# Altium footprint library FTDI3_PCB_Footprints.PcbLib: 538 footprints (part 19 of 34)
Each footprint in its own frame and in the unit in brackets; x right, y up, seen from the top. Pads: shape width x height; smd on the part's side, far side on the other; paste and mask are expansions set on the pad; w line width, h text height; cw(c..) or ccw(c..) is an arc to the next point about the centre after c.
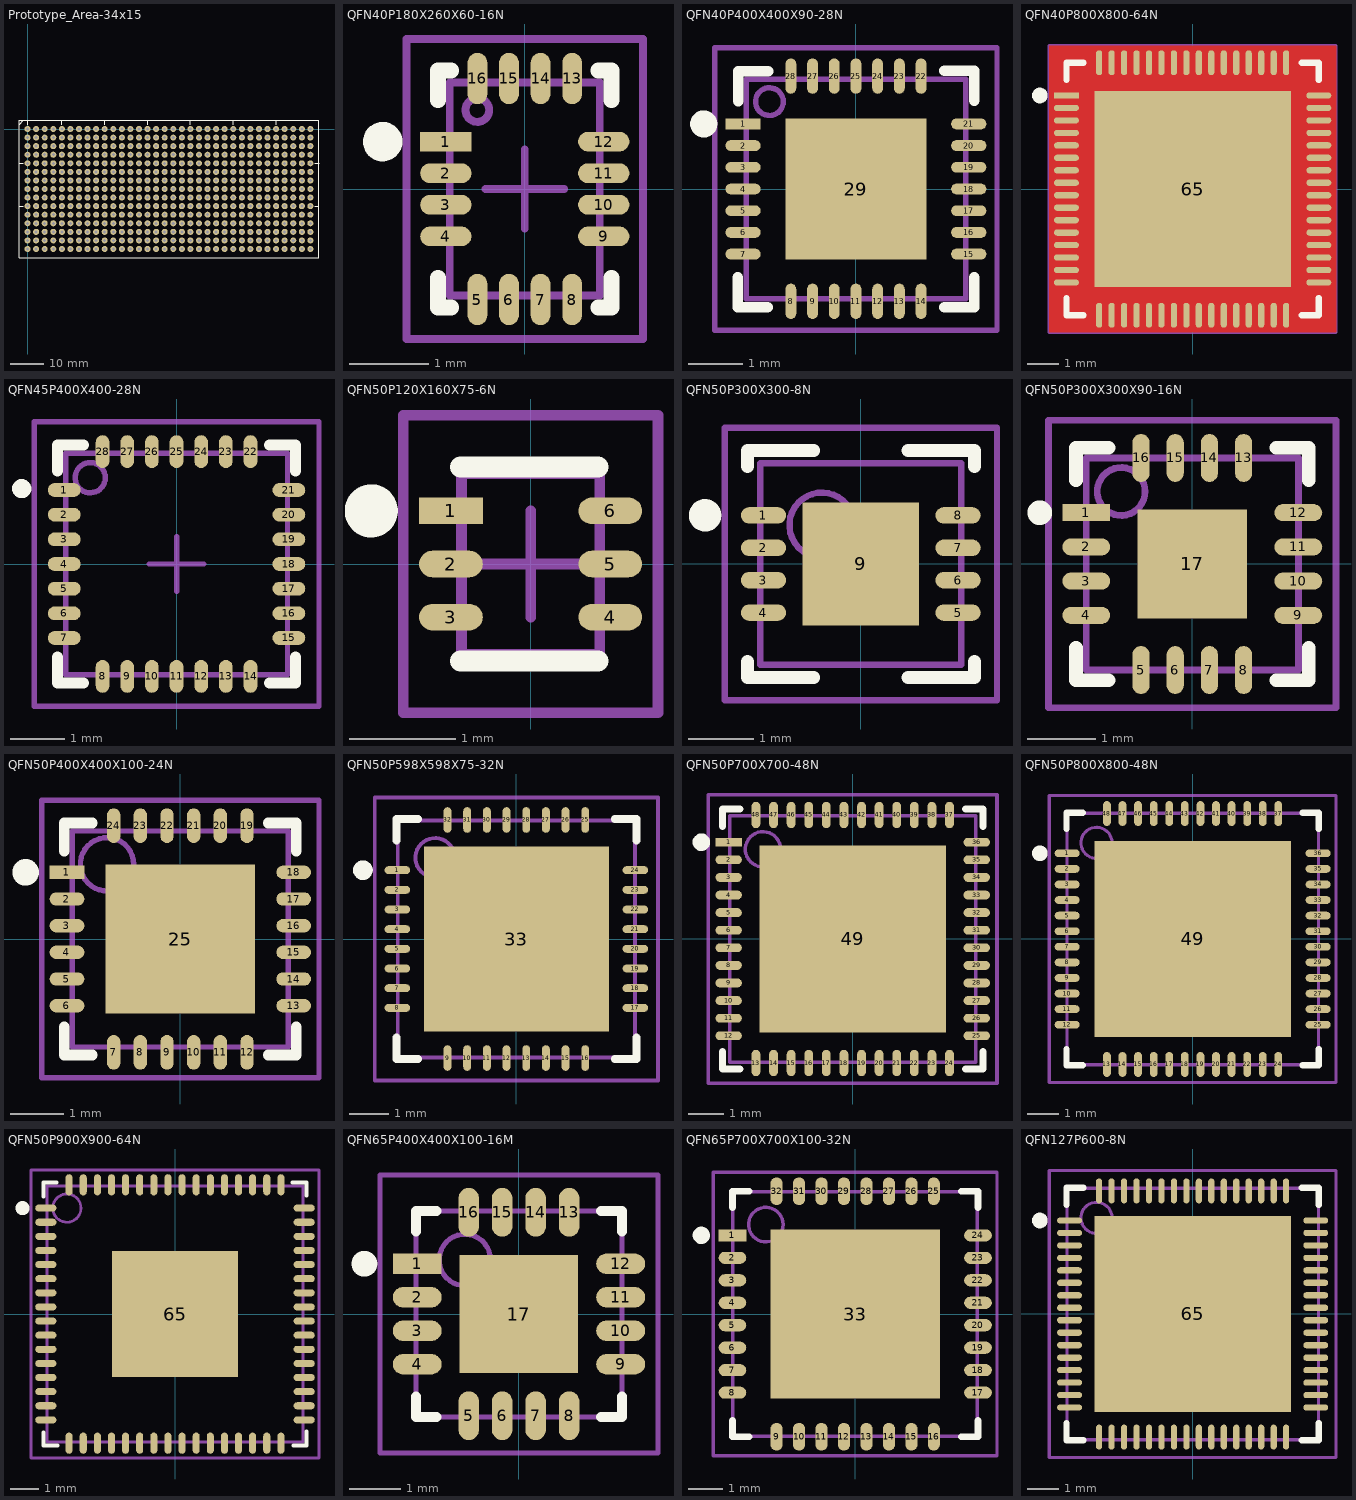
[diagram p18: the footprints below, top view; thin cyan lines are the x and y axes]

## Prototype_Area-34x15 [mm] "Prototype area; 34 cols x 15 rows"
pads (510):
  round 1.8 hole 0.9: 1(0,0) 2(2.54,0) 3(5.08,0) 4(7.62,0) 5(10.16,0) 6(12.7,0) 7(15.24,0) 8(17.78,0) 9(20.32,0) 10(22.86,0) 11(25.4,0) 12(27.94,0) 13(30.48,0) 14(33.02,0) 15(35.56,0) 16(38.1,0) 17(40.64,0) 18(43.18,0) 19(45.72,0) 20(48.26,0) 21(50.8,0) 22(53.34,0) 23(55.88,0) 24(58.42,0) 25(60.96,0) 26(63.5,0) 27(66.04,0) 28(68.58,0) 29(71.12,0) 30(73.66,0) 31(76.2,0) 32(78.74,0) 33(81.28,0) 34(83.82,0) ""(0,-35.56) ""(0,-33.02) ""(0,-30.48) ""(0,-27.94) ""(0,-25.4) ""(0,-22.86) ""(0,-20.32) ""(0,-17.78) ""(0,-15.24) ""(0,-12.7) ""(0,-10.16) ""(0,-7.62) ""(0,-5.08) ""(0,-2.54) ""(2.54,-35.56) ""(2.54,-33.02) ""(2.54,-30.48) ""(2.54,-27.94) ""(2.54,-25.4) ""(2.54,-22.86) ""(2.54,-20.32) ""(2.54,-17.78) ""(2.54,-15.24) ""(2.54,-12.7) ""(2.54,-10.16) ""(2.54,-7.62) ""(2.54,-5.08) ""(2.54,-2.54) ""(5.08,-35.56) ""(5.08,-33.02) ""(5.08,-30.48) ""(5.08,-27.94) ""(5.08,-25.4) ""(5.08,-22.86) ""(5.08,-20.32) ""(5.08,-17.78) ""(5.08,-15.24) ""(5.08,-12.7) ""(5.08,-10.16) ""(5.08,-7.62) ""(5.08,-5.08) ""(5.08,-2.54) ""(7.62,-35.56) ""(7.62,-33.02) ""(7.62,-30.48) ""(7.62,-27.94) ""(7.62,-25.4) ""(7.62,-22.86) ""(7.62,-20.32) ""(7.62,-17.78) ""(7.62,-15.24) ""(7.62,-12.7) ""(7.62,-10.16) ""(7.62,-7.62) ""(7.62,-5.08) ""(7.62,-2.54) ""(10.16,-35.56) ""(10.16,-33.02) ""(10.16,-30.48) ""(10.16,-27.94) ""(10.16,-25.4) ""(10.16,-22.86) ""(10.16,-20.32) ""(10.16,-17.78) ""(10.16,-15.24) ""(10.16,-12.7) ""(10.16,-10.16) ""(10.16,-7.62) ""(10.16,-5.08) ""(10.16,-2.54) ""(12.7,-35.56) ""(12.7,-33.02) ""(12.7,-30.48) ""(12.7,-27.94) ""(12.7,-25.4) ""(12.7,-22.86) ""(12.7,-20.32) ""(12.7,-17.78) ""(12.7,-15.24) ""(12.7,-12.7) ""(12.7,-10.16) ""(12.7,-7.62) ""(12.7,-5.08) ""(12.7,-2.54) ""(15.24,-35.56) ""(15.24,-33.02) ""(15.24,-30.48) ""(15.24,-27.94) ""(15.24,-25.4) ""(15.24,-22.86) ""(15.24,-20.32) ""(15.24,-17.78) ""(15.24,-15.24) ""(15.24,-12.7) ""(15.24,-10.16) ""(15.24,-7.62) ""(15.24,-5.08) ""(15.24,-2.54) ""(17.78,-35.56) ""(17.78,-33.02) ""(17.78,-30.48) ""(17.78,-27.94) ""(17.78,-25.4) ""(17.78,-22.86) ""(17.78,-20.32) ""(17.78,-17.78) ""(17.78,-15.24) ""(17.78,-12.7) ""(17.78,-10.16) ""(17.78,-7.62) ""(17.78,-5.08) ""(17.78,-2.54) ""(20.32,-35.56) ""(20.32,-33.02) ""(20.32,-30.48) ""(20.32,-27.94) ""(20.32,-25.4) ""(20.32,-22.86) ""(20.32,-20.32) ""(20.32,-17.78) ""(20.32,-15.24) ""(20.32,-12.7) ""(20.32,-10.16) ""(20.32,-7.62) ""(20.32,-5.08) ""(20.32,-2.54) ""(22.86,-35.56) ""(22.86,-33.02) ""(22.86,-30.48) ""(22.86,-27.94) ""(22.86,-25.4) ""(22.86,-22.86) ""(22.86,-20.32) ""(22.86,-17.78) ""(22.86,-15.24) ""(22.86,-12.7) ""(22.86,-10.16) ""(22.86,-7.62) ""(22.86,-5.08) ""(22.86,-2.54) ""(25.4,-35.56) ""(25.4,-33.02) ""(25.4,-30.48) ""(25.4,-27.94) ""(25.4,-25.4) ""(25.4,-22.86) ""(25.4,-20.32) ""(25.4,-17.78) ""(25.4,-15.24) ""(25.4,-12.7) ""(25.4,-10.16) ""(25.4,-7.62) ""(25.4,-5.08) ""(25.4,-2.54) ""(27.94,-35.56) ""(27.94,-33.02) ""(27.94,-30.48) ""(27.94,-27.94) ""(27.94,-25.4) ""(27.94,-22.86) ""(27.94,-20.32) ""(27.94,-17.78) ""(27.94,-15.24) ""(27.94,-12.7) ""(27.94,-10.16) ""(27.94,-7.62) ""(27.94,-5.08) ""(27.94,-2.54) ""(30.48,-35.56) ""(30.48,-33.02) ""(30.48,-30.48) ""(30.48,-27.94) ""(30.48,-25.4) ""(30.48,-22.86) ""(30.48,-20.32) ""(30.48,-17.78) ""(30.48,-15.24) ""(30.48,-12.7) ""(30.48,-10.16) ""(30.48,-7.62) ""(30.48,-5.08) ""(30.48,-2.54) ""(33.02,-35.56) ""(33.02,-33.02) ""(33.02,-30.48) ""(33.02,-27.94) ""(33.02,-25.4) ""(33.02,-22.86) ""(33.02,-20.32) ""(33.02,-17.78) ""(33.02,-15.24) ""(33.02,-12.7) ""(33.02,-10.16) ""(33.02,-7.62) ""(33.02,-5.08) ""(33.02,-2.54) ""(35.56,-35.56) ""(35.56,-33.02) ""(35.56,-30.48) ""(35.56,-27.94) ""(35.56,-25.4) ""(35.56,-22.86) ""(35.56,-20.32) ""(35.56,-17.78) ""(35.56,-15.24) ""(35.56,-12.7) ""(35.56,-10.16) ""(35.56,-7.62) ""(35.56,-5.08) ""(35.56,-2.54) ""(38.1,-35.56) ""(38.1,-33.02) ""(38.1,-30.48) ""(38.1,-27.94) ""(38.1,-25.4) ""(38.1,-22.86) ""(38.1,-20.32) ""(38.1,-17.78) ""(38.1,-15.24) ""(38.1,-12.7) ""(38.1,-10.16) ""(38.1,-7.62) ""(38.1,-5.08) ""(38.1,-2.54) ""(40.64,-35.56) ""(40.64,-33.02) ""(40.64,-30.48) ""(40.64,-27.94) ""(40.64,-25.4) ""(40.64,-22.86) ""(40.64,-20.32) ""(40.64,-17.78) ""(40.64,-15.24) ""(40.64,-12.7) ""(40.64,-10.16) ""(40.64,-7.62) ""(40.64,-5.08) ""(40.64,-2.54) ""(43.18,-35.56) ""(43.18,-33.02) ""(43.18,-30.48) ""(43.18,-27.94) ""(43.18,-25.4) ""(43.18,-22.86) ""(43.18,-20.32) ""(43.18,-17.78) ""(43.18,-15.24) ""(43.18,-12.7) ""(43.18,-10.16) ""(43.18,-7.62) ""(43.18,-5.08) ""(43.18,-2.54) ""(45.72,-35.56) ""(45.72,-33.02) ""(45.72,-30.48) ""(45.72,-27.94) ""(45.72,-25.4) ""(45.72,-22.86) ""(45.72,-20.32) ""(45.72,-17.78) ""(45.72,-15.24) ""(45.72,-12.7) ""(45.72,-10.16) ""(45.72,-7.62) ""(45.72,-5.08) ""(45.72,-2.54) ""(48.26,-35.56) ""(48.26,-33.02) ""(48.26,-30.48) ""(48.26,-27.94) ""(48.26,-25.4) ""(48.26,-22.86) ""(48.26,-20.32) ""(48.26,-17.78) ""(48.26,-15.24) ""(48.26,-12.7) ""(48.26,-10.16) ""(48.26,-7.62) ""(48.26,-5.08) ""(48.26,-2.54) ""(50.8,-35.56) ""(50.8,-33.02) ""(50.8,-30.48) ""(50.8,-27.94) ""(50.8,-25.4) ""(50.8,-22.86) ""(50.8,-20.32) ""(50.8,-17.78) ""(50.8,-15.24) ""(50.8,-12.7) ""(50.8,-10.16) ""(50.8,-7.62) ""(50.8,-5.08) ""(50.8,-2.54) ""(53.34,-35.56) ""(53.34,-33.02) ""(53.34,-30.48) ""(53.34,-27.94) ""(53.34,-25.4) ""(53.34,-22.86) ""(53.34,-20.32) ""(53.34,-17.78) ""(53.34,-15.24) ""(53.34,-12.7) ""(53.34,-10.16) ""(53.34,-7.62) ""(53.34,-5.08) ""(53.34,-2.54) ""(55.88,-35.56) ""(55.88,-33.02) ""(55.88,-30.48) ""(55.88,-27.94) ""(55.88,-25.4) ""(55.88,-22.86) ""(55.88,-20.32) ""(55.88,-17.78) ""(55.88,-15.24) ""(55.88,-12.7) ""(55.88,-10.16) ""(55.88,-7.62) ""(55.88,-5.08) ""(55.88,-2.54) ""(58.42,-35.56) ""(58.42,-33.02) ""(58.42,-30.48) ""(58.42,-27.94) ""(58.42,-25.4) ""(58.42,-22.86) ""(58.42,-20.32) ""(58.42,-17.78) ""(58.42,-15.24) ""(58.42,-12.7) ""(58.42,-10.16) ""(58.42,-7.62) ""(58.42,-5.08) ""(58.42,-2.54) ""(60.96,-35.56) ""(60.96,-33.02) ""(60.96,-30.48) ""(60.96,-27.94) ""(60.96,-25.4) ""(60.96,-22.86) ""(60.96,-20.32) ""(60.96,-17.78) ""(60.96,-15.24) ""(60.96,-12.7) ""(60.96,-10.16) ""(60.96,-7.62) ""(60.96,-5.08) ""(60.96,-2.54) ""(63.5,-35.56) ""(63.5,-33.02) ""(63.5,-30.48) ""(63.5,-27.94) ""(63.5,-25.4) ""(63.5,-22.86) ""(63.5,-20.32) ""(63.5,-17.78) ""(63.5,-15.24) ""(63.5,-12.7) ""(63.5,-10.16) ""(63.5,-7.62) ""(63.5,-5.08) ""(63.5,-2.54) ""(66.04,-35.56) ""(66.04,-33.02) ""(66.04,-30.48) ""(66.04,-27.94) ""(66.04,-25.4) ""(66.04,-22.86) ""(66.04,-20.32) ""(66.04,-17.78) ""(66.04,-15.24) ""(66.04,-12.7) ""(66.04,-10.16) ""(66.04,-7.62) ""(66.04,-5.08) ""(66.04,-2.54) ""(68.58,-35.56) ""(68.58,-33.02) ""(68.58,-30.48) ""(68.58,-27.94) ""(68.58,-25.4) ""(68.58,-22.86) ""(68.58,-20.32) ""(68.58,-17.78) ""(68.58,-15.24) ""(68.58,-12.7) ""(68.58,-10.16) ""(68.58,-7.62) ""(68.58,-5.08) ""(68.58,-2.54) ""(71.12,-35.56) ""(71.12,-33.02) ""(71.12,-30.48) ""(71.12,-27.94) ""(71.12,-25.4) ""(71.12,-22.86) ""(71.12,-20.32) ""(71.12,-17.78) ""(71.12,-15.24) ""(71.12,-12.7) ""(71.12,-10.16) ""(71.12,-7.62) ""(71.12,-5.08) ""(71.12,-2.54) ""(73.66,-35.56) ""(73.66,-33.02) ""(73.66,-30.48) ""(73.66,-27.94) ""(73.66,-25.4) ""(73.66,-22.86) ""(73.66,-20.32) ""(73.66,-17.78) ""(73.66,-15.24) ""(73.66,-12.7) ""(73.66,-10.16) ""(73.66,-7.62) ""(73.66,-5.08) ""(73.66,-2.54) ""(76.2,-35.56) ""(76.2,-33.02) ""(76.2,-30.48) ""(76.2,-27.94) ""(76.2,-25.4) ""(76.2,-22.86) ""(76.2,-20.32) ""(76.2,-17.78) ""(76.2,-15.24) ""(76.2,-12.7) ""(76.2,-10.16) ""(76.2,-7.62) ""(76.2,-5.08) ""(76.2,-2.54) ""(78.74,-35.56) ""(78.74,-33.02) ""(78.74,-30.48) ""(78.74,-27.94) ""(78.74,-25.4) ""(78.74,-22.86) ""(78.74,-20.32) ""(78.74,-17.78) ""(78.74,-15.24) ""(78.74,-12.7) ""(78.74,-10.16) ""(78.74,-7.62) ""(78.74,-5.08) ""(78.74,-2.54) ""(81.28,-35.56) ""(81.28,-33.02) ""(81.28,-30.48) ""(81.28,-27.94) ""(81.28,-25.4) ""(81.28,-22.86) ""(81.28,-20.32) ""(81.28,-17.78) ""(81.28,-15.24) ""(81.28,-12.7) ""(81.28,-10.16) ""(81.28,-7.62) ""(81.28,-5.08) ""(81.28,-2.54) ""(83.82,-35.56) ""(83.82,-33.02) ""(83.82,-30.48) ""(83.82,-27.94) ""(83.82,-25.4) ""(83.82,-22.86) ""(83.82,-20.32) ""(83.82,-17.78) ""(83.82,-15.24) ""(83.82,-12.7) ""(83.82,-10.16) ""(83.82,-7.62) ""(83.82,-5.08) ""(83.82,-2.54)
Top Overlay:
  lines w0.2: -2.54,-22.86 -1.27,-22.86 ; -2.54,-10.16 -1.27,-10.16 ; 85.09,-22.85 86.36,-22.85 ; 85.1,-10.16 86.37,-10.16
  lines w0.254: -2.54,1.27 -1.27,2.54 ; 0,1.27 0,2.54 ; 10.16,1.27 10.16,2.54 ; 22.86,1.27 22.86,2.54 ; 35.56,1.27 35.56,2.54 ; 48.26,1.27 48.26,2.54 ; 60.96,1.27 60.96,2.54 ; 73.66,1.27 73.66,2.54 ; -2.54,-38.1 -2.54,2.54 86.36,2.54 86.36,-38.1 -2.54,-38.1

## QFN40P180X260X60-16N [mm] "QFN, 16-Leads, Body 2.7x1.9mm (max), Pitch 0.40mm, IPC Medium Density"
height 0.6
pads (16):
  rect 0.65x0.25 smd: 1(-1,0.6)
  oval 0.65x0.25 smd: 2(-1,0.2) 3(-1,-0.2) 4(-1,-0.6) 9(1,-0.6) 10(1,-0.2) 11(1,0.2) 12(1,0.6)
  oval 0.25x0.65 smd: 5(-0.6,-1.4) 6(-0.2,-1.4) 7(0.2,-1.4) 8(0.6,-1.4) 13(0.6,1.4) 14(0.2,1.4) 15(-0.2,1.4) 16(-0.6,1.4)
Top Overlay:
  circle w0.25: c-1.8,0.6 r0.125
  lines w0.2: -1.1,-1.125 -1.1,-1.5 -0.93,-1.5 ; -1.1,1.125 -1.1,1.5 -0.93,1.5 ; 0.93,-1.5 1.1,-1.5 1.1,-1.125 ; 0.93,1.5 1.1,1.5 1.1,1.125
M13_Assembly_Info:
  circle w0.1: c-0.6,1 r0.15
  lines w0.1: -0.95,-1.35 -0.95,1.35 0.95,1.35 0.95,-1.35 -0.95,-1.35
M15_Country_Yard:
  lines w0.1: -0.5,0 0.5,0 ; 0,-0.5 0,0.5 ; -1.5,-1.9 -1.5,1.9 1.5,1.9 1.5,-1.9 -1.5,-1.9
3D body: height 0.6, standoff 0.05, extent -0.95,-1.35 0.95,1.35

## QFN40P400X400X90-28N [mm] "QFN, 28-Leads, Body 4x4mm (max), Pitch 0.40mm, IPC Medium Density"
height 0.9
pads (29):
  rect 0.65x0.2 smd: 1(-2.08,1.2)
  oval 0.65x0.2 smd: 2(-2.08,0.8) 3(-2.08,0.4) 4(-2.08,0) 5(-2.08,-0.4) 6(-2.08,-0.8) 7(-2.08,-1.2) 15(2.08,-1.2) 16(2.08,-0.8) 17(2.08,-0.4) 18(2.08,0) 19(2.08,0.4) 20(2.08,0.8) 21(2.08,1.2)
  oval 0.2x0.65 smd: 8(-1.2,-2.07) 9(-0.8,-2.07) 10(-0.4,-2.07) 11(0,-2.07) 12(0.4,-2.07) 13(0.8,-2.07) 14(1.2,-2.07) 22(1.2,2.08) 23(0.8,2.08) 24(0.4,2.08) 25(0,2.08) 26(-0.4,2.08) 27(-0.8,2.08) 28(-1.2,2.08)
  rect 2.6x2.6 smd: 29(0,0)
Top Overlay:
  circle w0.25: c-2.805,1.2 r0.125
  lines w0.2: -2.18,-1.63 -2.18,-2.18 -1.63,-2.18 ; -2.17,1.62 -2.17,2.17 -1.62,2.17 ; 1.63,-2.18 2.18,-2.18 2.18,-1.63 ; 1.63,2.18 2.18,2.18 2.18,1.63
M13_Assembly_Info:
  circle w0.1: c-1.595,1.61 r0.255
  lines w0.1: -2.025,-2.025 2.025,-2.025 2.025,2.025 -2.025,2.025 -2.025,-2.025
M15_Country_Yard:
  lines w0.1: -0.5,0 0.5,0 ; 0,-0.5 0,0.5 ; -2.6,-2.6 2.6,-2.6 2.6,2.6 -2.6,2.6 -2.6,-2.6
3D body: height 0.9, standoff 0.05, extent -2.025,-2.025 2.025,2.025

## QFN40P800X800-64N [mm] "QFN, 64-Leads, Body 8x8mm (max), Pitch 0.40mm, IPC Medium Density"
height 1
pads (65):
  rect 0.8x0.2 smd: 1(-4.05,3)
  oval 0.8x0.2 smd: 2(-4.05,2.6) 3(-4.05,2.2) 4(-4.05,1.8) 5(-4.05,1.4) 6(-4.05,1) 7(-4.05,0.6) 8(-4.05,0.2) 9(-4.05,-0.2) 10(-4.05,-0.6) 11(-4.05,-1) 12(-4.05,-1.4) 13(-4.05,-1.8) 14(-4.05,-2.2) 15(-4.05,-2.6) 16(-4.05,-3) 33(4.05,-3) 34(4.05,-2.6) 35(4.05,-2.2) 36(4.05,-1.8) 37(4.05,-1.4) 38(4.05,-1) 39(4.05,-0.6) 40(4.05,-0.2) 41(4.05,0.2) 42(4.05,0.6) 43(4.05,1) 44(4.05,1.4) 45(4.05,1.8) 46(4.05,2.2) 47(4.05,2.6) 48(4.05,3)
  oval 0.2x0.8 smd: 17(-3,-4.05) 18(-2.6,-4.05) 19(-2.2,-4.05) 20(-1.8,-4.05) 21(-1.4,-4.05) 22(-1,-4.05) 23(-0.6,-4.05) 24(-0.2,-4.05) 25(0.2,-4.05) 26(0.6,-4.05) 27(1,-4.05) 28(1.4,-4.05) 29(1.8,-4.05) 30(2.2,-4.05) 31(2.6,-4.05) 32(3,-4.05) 49(3,4.05) 50(2.6,4.05) 51(2.2,4.05) 52(1.8,4.05) 53(1.4,4.05) 54(1,4.05) 55(0.6,4.05) 56(0.2,4.05) 57(-0.2,4.05) 58(-0.6,4.05) 59(-1,4.05) 60(-1.4,4.05) 61(-1.8,4.05) 62(-2.2,4.05) 63(-2.6,4.05) 64(-3,4.05)
  rect 6.3x6.3 smd: 65(0,0)
Top Layer:
  pour cut-out: -4.6,4.6 4.6,4.6 4.6,-4.6 -4.6,-4.6
Top Overlay:
  circle w0.25: c-4.9,3 r0.125
  lines w0.2: -4.05,-3.5 -4.05,-4.05 -3.5,-4.05 ; -4.05,3.5 -4.05,4.05 -3.5,4.05 ; 3.5,-4.05 4.05,-4.05 4.05,-3.5 ; 3.5,4.05 4.05,4.05 4.05,3.5
M13_Assembly_Info:
  circle w0.1: c-3.085,3.085 r0.5
  lines w0.1: -4.035,-4.035 -4.035,4.035 4.035,4.035 4.035,-4.035 -4.035,-4.035
M15_Country_Yard:
  lines w0.1: -0.5,0 0.5,0 ; 0,-0.5 0,0.5 ; -4.6,-4.6 -4.6,4.6 4.6,4.6 4.6,-4.6 -4.6,-4.6
3D body: height 1, standoff 0.05, extent -4.035,-4.035 4.035,4.035

## QFN45P400X400-28N [mm] "QFN, 28-Leads, Body 4.1x4.1mm (max), Pitch 0.45mm, IPC Medium Density"
height 0.775
pads (29):
  oval 0.6x0.25 smd: 1(-2.05,1.35) 2(-2.05,0.9) 3(-2.05,0.45) 4(-2.05,0) 5(-2.05,-0.45) 6(-2.05,-0.9) 7(-2.05,-1.35) 15(2.05,-1.35) 16(2.05,-0.9) 17(2.05,-0.45) 18(2.05,0) 19(2.05,0.45) 20(2.05,0.9) 21(2.05,1.35)
  oval 0.25x0.6 smd: 8(-1.35,-2.05) 9(-0.9,-2.05) 10(-0.45,-2.05) 11(0,-2.05) 12(0.45,-2.05) 13(0.9,-2.05) 14(1.35,-2.05) 22(1.35,2.05) 23(0.9,2.05) 24(0.45,2.05) 25(0,2.05) 26(-0.45,2.05) 27(-0.9,2.05) 28(-1.35,2.05)
  rect 0x0 smd: 29(0,0)
Top Overlay:
  circle w0.25: c-2.825,1.375 r0.05
  lines w0.2: -2.175,-1.7 -2.175,-2.175 -1.7,-2.175 ; -2.175,1.7 -2.175,2.175 -1.7,2.175 ; 1.7,-2.17 2.175,-2.17 2.175,-1.695 ; 1.7,2.175 2.175,2.175 2.175,1.7
M13_Assembly_Info:
  circle w0.1: c-1.575,1.575 r0.275
  lines w0.1: -2.025,-2.025 -2.025,2.025 2.025,2.025 2.025,-2.025 -2.025,-2.025
M15_Country_Yard:
  lines w0.1: -0.5,0 0.5,0 ; 0,-0.5 0,0.5 ; -2.6,-2.6 -2.6,2.6 2.6,2.6 2.6,-2.6 -2.6,-2.6
3D body: height 0.77, standoff 0.05, extent -2.025,-2.025 2.025,2.025

## QFN50P120X160X75-6N [mm] "QFN, 6-Leads, Body 1.7x1.3mm (max), Pitch 0.50mm, IPC Medium Density"
height 0.75
pads (6):
  rect 0.6x0.25 smd: 1(-0.75,0.5)
  oval 0.6x0.25 smd: 2(-0.75,0) 3(-0.75,-0.5) 4(0.75,-0.5) 5(0.75,0) 6(0.75,0.5)
Top Overlay:
  circle w0.25: c-1.5,0.5 r0.125
  lines w0.2: -0.66,-0.914 0.635,-0.914 ; -0.66,0.914 0.635,0.914
M13_Assembly_Info:
  lines w0.1: -0.65,-0.85 -0.65,0.85 0.65,0.85 0.65,-0.85 -0.65,-0.85
M15_Country_Yard:
  lines w0.1: -0.5,0 0.5,0 ; 0,-0.5 0,0.5 ; -1.2,-1.4 1.2,-1.4 1.2,1.4 -1.2,1.4 -1.2,-1.4
3D body: height 0.75, standoff 0.01, extent -0.65,-0.85 0.65,0.85

## QFN50P300X300-8N [mm] "QFN, 8-Leads, Body 3.1x3.1mm (max), Pitch 0.50mm, IPC Medium Density"
height 0.85
pads (9):
  oval 0.7x0.25 smd: 1(-1.5,0.75) 2(-1.5,0.25) 3(-1.5,-0.25) 4(-1.5,-0.75) 5(1.5,-0.75) 6(1.5,-0.25) 7(1.5,0.25) 8(1.5,0.75)
  rect 1.8x1.9 smd: 9(0,0)
Top Overlay:
  circle w0.25: c-2.4,0.75 r0.125
  lines w0.2: -1.75,-1.5 -1.75,-1.75 -0.725,-1.75 ; -1.75,1.5 -1.75,1.75 -0.725,1.75 ; 0.725,-1.75 1.75,-1.75 1.75,-1.5 ; 0.725,1.75 1.75,1.75 1.75,1.5
M13_Assembly_Info:
  circle w0.1: c-0.6,0.6 r0.5
  lines w0.1: -1.55,-1.55 1.55,-1.55 1.55,1.55 -1.55,1.55 -1.55,-1.55
M15_Country_Yard:
  lines w0.1: -0.5,0 0.5,0 ; 0,-0.5 0,0.5 ; -2.1,-2.1 2.1,-2.1 2.1,2.1 -2.1,2.1 -2.1,-2.1
3D body: height 0.85, standoff 0.05, extent -1.55,-1.55 1.55,1.55

## QFN50P300X300X90-16N [mm] "QFN, 16-Leads, Body 3.1x3.1mm (max), Pitch 0.50mm, IPC Medium Density"
height 0.9
pads (17):
  rect 0.7x0.25 smd: 1(-1.55,0.75)
  oval 0.7x0.25 smd: 2(-1.55,0.25) 3(-1.55,-0.25) 4(-1.55,-0.75) 9(1.55,-0.75) 10(1.55,-0.25) 11(1.55,0.25) 12(1.55,0.75)
  oval 0.25x0.7 smd: 5(-0.75,-1.55) 6(-0.25,-1.55) 7(0.25,-1.55) 8(0.75,-1.55) 13(0.75,1.55) 14(0.25,1.55) 15(-0.25,1.55) 16(-0.75,1.55)
  rect 1.6x1.6 smd: 17(0,0)
Top Overlay:
  circle w0.25: c-2.23,0.75 r0.055
  lines w0.2: -1.7,-1.225 -1.7,-1.7 -1.225,-1.7 ; -1.7,1.225 -1.7,1.7 -1.225,1.7 ; 1.225,-1.7 1.7,-1.7 1.7,-1.225 ; 1.225,1.7 1.7,1.7 1.7,1.225
M13_Assembly_Info:
  circle w0.1: c-1.04,1.06 r0.35
  lines w0.1: -1.55,-1.55 1.55,-1.55 1.55,1.55 -1.55,1.55 -1.55,-1.55
M15_Country_Yard:
  lines w0.1: -0.5,0 0.5,0 ; 0,-0.5 0,0.5 ; -2.1,-2.1 2.1,-2.1 2.1,2.1 -2.1,2.1 -2.1,-2.1
3D body: height 0.8, standoff 0.05, extent -1.55,-1.55 1.55,1.55

## QFN50P400X400X100-24N [mm] "QFN, 24-Leads, Body 4.1x4.1mm (max), Pitch 0.50mm, IPC Medium Density"
height 1
pads (25):
  rect 0.65x0.25 smd: 1(-2.125,1.25)
  oval 0.65x0.25 smd: 2(-2.125,0.75) 3(-2.125,0.25) 4(-2.125,-0.25) 5(-2.125,-0.75) 6(-2.125,-1.25) 13(2.125,-1.25) 14(2.125,-0.75) 15(2.125,-0.25) 16(2.125,0.25) 17(2.125,0.75) 18(2.125,1.25)
  oval 0.25x0.65 smd: 7(-1.25,-2.125) 8(-0.75,-2.125) 9(-0.25,-2.125) 10(0.25,-2.125) 11(0.75,-2.125) 12(1.25,-2.125) 19(1.25,2.125) 20(0.75,2.125) 21(0.25,2.125) 22(-0.25,2.125) 23(-0.75,2.125) 24(-1.25,2.125)
  rect 2.8x2.8 smd: 25(0,0)
Top Overlay:
  circle w0.25: c-2.9,1.25 r0.125
  lines w0.2: -2.175,-1.65 -2.175,-2.175 -1.65,-2.175 ; -2.175,1.65 -2.175,2.175 -1.65,2.175 ; 1.65,-2.175 2.175,-2.175 2.175,-1.65 ; 1.65,2.175 2.175,2.175 2.175,1.65
M13_Assembly_Info:
  circle w0.1: c-1.375,1.4 r0.5
  lines w0.1: -2.025,-2.025 -2.025,2.025 2.025,2.025 2.025,-2.025 -2.025,-2.025
M15_Country_Yard:
  lines w0.1: -0.5,0 0.5,0 ; 0,-0.5 0,0.5 ; -2.6,-2.6 -2.6,2.6 2.6,2.6 2.6,-2.6 -2.6,-2.6
3D body: height 1, standoff 0.05, extent -2.025,-2.025 2.025,2.025

## QFN50P598X598X75-32N [mm] "QFN, 32-Leads, Body 6.0x6.0mm (max), Pitch 0.50mm, IPC Medium Density"
height 0.75
pads (33):
  oval 0.65x0.2 smd: 1(-3.025,1.75) 2(-3.025,1.25) 3(-3.025,0.75) 4(-3.025,0.25) 5(-3.025,-0.25) 6(-3.025,-0.75) 7(-3.025,-1.25) 8(-3.025,-1.75) 17(3.025,-1.75) 18(3.025,-1.25) 19(3.025,-0.75) 20(3.025,-0.25) 21(3.025,0.25) 22(3.025,0.75) 23(3.025,1.25) 24(3.025,1.75)
  oval 0.2x0.65 smd: 9(-1.75,-3.025) 10(-1.25,-3.025) 11(-0.75,-3.025) 12(-0.25,-3.025) 13(0.25,-3.025) 14(0.75,-3.025) 15(1.25,-3.025) 16(1.75,-3.025) 25(1.75,3.025) 26(1.25,3.025) 27(0.75,3.025) 28(0.25,3.025) 29(-0.25,3.025) 30(-0.75,3.025) 31(-1.25,3.025) 32(-1.75,3.025)
  rect 4.7x4.7 smd: 33(0,0)
Top Overlay:
  circle w0.25: c-3.9,1.75 r0.125
  lines w0.2: -3.05,-2.5 -3.05,-3.05 -2.5,-3.05 ; -3.05,2.5 -3.05,3.05 -2.5,3.05 ; 2.5,-3.05 3.05,-3.05 3.05,-2.5 ; 2.5,3.05 3.05,3.05 3.05,2.5
M13_Assembly_Info:
  circle w0.1: c-2.065,2.065 r0.5
  lines w0.1: -3.015,-3.015 -3.015,3.015 3.015,3.015 3.015,-3.015 -3.015,-3.015
M15_Country_Yard:
  lines w0.1: -0.5,0 0.5,0 ; 0,-0.5 0,0.5 ; -3.6,-3.6 -3.6,3.6 3.6,3.6 3.6,-3.6 -3.6,-3.6
3D body: height 0.75, standoff 0.01, extent -3.015,-3.015 3.015,3.015

## QFN50P700X700-48N [mm] "QFN, 48-Leads, Body 7.0x7.0mm (max), Pitch 0.50mm, IPC Medium Density"
height 1
pads (49):
  rect 0.75x0.25 smd: 1(-3.525,2.75)
  oval 0.75x0.25 smd: 2(-3.525,2.25) 3(-3.525,1.75) 4(-3.525,1.25) 5(-3.525,0.75) 6(-3.525,0.25) 7(-3.525,-0.25) 8(-3.525,-0.75) 9(-3.525,-1.25) 10(-3.525,-1.75) 11(-3.525,-2.25) 12(-3.525,-2.75) 25(3.525,-2.75) 26(3.525,-2.25) 27(3.525,-1.75) 28(3.525,-1.25) 29(3.525,-0.75) 30(3.525,-0.25) 31(3.525,0.25) 32(3.525,0.75) 33(3.525,1.25) 34(3.525,1.75) 35(3.525,2.25) 36(3.525,2.75)
  oval 0.25x0.75 smd: 13(-2.75,-3.525) 14(-2.25,-3.525) 15(-1.75,-3.525) 16(-1.25,-3.525) 17(-0.75,-3.525) 18(-0.25,-3.525) 19(0.25,-3.525) 20(0.75,-3.525) 21(1.25,-3.525) 22(1.75,-3.525) 23(2.25,-3.525) 24(2.75,-3.525) 37(2.75,3.525) 38(2.25,3.525) 39(1.75,3.525) 40(1.25,3.525) 41(0.75,3.525) 42(0.25,3.525) 43(-0.25,3.525) 44(-0.75,3.525) 45(-1.25,3.525) 46(-1.75,3.525) 47(-2.25,3.525) 48(-2.75,3.525)
  rect 5.3x5.3 smd: 49(0,0)
Top Overlay:
  circle w0.25: c-4.3,2.75 r0.125
  lines w0.2: -3.7,-3.2 -3.7,-3.7 -3.2,-3.7 ; -3.7,3.2 -3.7,3.7 -3.2,3.7 ; 3.2,-3.7 3.7,-3.7 3.7,-3.2 ; 3.2,3.7 3.7,3.7 3.7,3.2
M13_Assembly_Info:
  circle w0.1: c-2.55,2.55 r0.5
  lines w0.1: -3.5,-3.5 -3.5,3.5 3.5,3.5 3.5,-3.5 -3.5,-3.5
M15_Country_Yard:
  lines w0.1: -0.5,0 0.5,0 ; 0,-0.5 0,0.5 ; -4.1,-4.1 -4.1,4.1 4.1,4.1 4.1,-4.1 -4.1,-4.1
3D body: height 1, standoff 0.05, extent -3.5,-3.5 3.5,3.5

## QFN50P800X800-48N [mm] "QFN, 48-Leads, Body 8.0x8.0mm (max), Pitch 0.50mm, IPC Medium Density"
height 1
pads (49):
  oval 0.8x0.25 smd: 1(-4.025,2.75) 2(-4.025,2.25) 3(-4.025,1.75) 4(-4.025,1.25) 5(-4.025,0.75) 6(-4.025,0.25) 7(-4.025,-0.25) 8(-4.025,-0.75) 9(-4.025,-1.25) 10(-4.025,-1.75) 11(-4.025,-2.25) 12(-4.025,-2.75) 25(4.025,-2.75) 26(4.025,-2.25) 27(4.025,-1.75) 28(4.025,-1.25) 29(4.025,-0.75) 30(4.025,-0.25) 31(4.025,0.25) 32(4.025,0.75) 33(4.025,1.25) 34(4.025,1.75) 35(4.025,2.25) 36(4.025,2.75)
  oval 0.25x0.8 smd: 13(-2.75,-4.025) 14(-2.25,-4.025) 15(-1.75,-4.025) 16(-1.25,-4.025) 17(-0.75,-4.025) 18(-0.25,-4.025) 19(0.25,-4.025) 20(0.75,-4.025) 21(1.25,-4.025) 22(1.75,-4.025) 23(2.25,-4.025) 24(2.75,-4.025) 37(2.75,4.025) 38(2.25,4.025) 39(1.75,4.025) 40(1.25,4.025) 41(0.75,4.025) 42(0.25,4.025) 43(-0.25,4.025) 44(-0.75,4.025) 45(-1.25,4.025) 46(-1.75,4.025) 47(-2.25,4.025) 48(-2.75,4.025)
  rect 6.3x6.3 smd: 49(0,0)
Top Overlay:
  circle w0.25: c-4.9,2.75 r0.125
  lines w0.2: -4.05,-3.525 -4.05,-4.05 -3.525,-4.05 ; -4.05,3.525 -4.05,4.05 -3.525,4.05 ; 3.525,-4.05 4.05,-4.05 4.05,-3.525 ; 3.525,4.05 4.05,4.05 4.05,3.525
M13_Assembly_Info:
  circle w0.1: c-3.085,3.085 r0.5
  lines w0.1: -4.035,-4.035 -4.035,4.035 4.035,4.035 4.035,-4.035 -4.035,-4.035
M15_Country_Yard:
  lines w0.1: -0.5,0 0.5,0 ; 0,-0.5 0,0.5 ; -4.6,-4.6 -4.6,4.6 4.6,4.6 4.6,-4.6 -4.6,-4.6
3D body: height 1, standoff 0.05, extent -4.035,-4.035 4.035,4.035

## QFN50P900X900-64N [mm] "QFN, 64-Leads, Body 9x9mm, Pitch 0.50mm, IPC Medium Density"
height 1
pads (65):
  oval 0.75x0.25 smd: 1(-4.575,3.75) 2(-4.575,3.25) 3(-4.575,2.75) 4(-4.575,2.25) 5(-4.575,1.75) 6(-4.575,1.25) 7(-4.575,0.75) 8(-4.575,0.25) 9(-4.575,-0.25) 10(-4.575,-0.75) 11(-4.575,-1.25) 12(-4.575,-1.75) 13(-4.575,-2.25) 14(-4.575,-2.75) 15(-4.575,-3.25) 16(-4.575,-3.75) 33(4.575,-3.75) 34(4.575,-3.25) 35(4.575,-2.75) 36(4.575,-2.25) 37(4.575,-1.75) 38(4.575,-1.25) 39(4.575,-0.75) 40(4.575,-0.25) 41(4.575,0.25) 42(4.575,0.75) 43(4.575,1.25) 44(4.575,1.75) 45(4.575,2.25) 46(4.575,2.75) 47(4.575,3.25) 48(4.575,3.75)
  oval 0.25x0.75 smd: 17(-3.75,-4.575) 18(-3.25,-4.575) 19(-2.75,-4.575) 20(-2.25,-4.575) 21(-1.75,-4.575) 22(-1.25,-4.575) 23(-0.75,-4.575) 24(-0.25,-4.575) 25(0.25,-4.575) 26(0.75,-4.575) 27(1.25,-4.575) 28(1.75,-4.575) 29(2.25,-4.575) 30(2.75,-4.575) 31(3.25,-4.575) 32(3.75,-4.575) 49(3.75,4.575) 50(3.25,4.575) 51(2.75,4.575) 52(2.25,4.575) 53(1.75,4.575) 54(1.25,4.575) 55(0.75,4.575) 56(0.25,4.575) 57(-0.25,4.575) 58(-0.75,4.575) 59(-1.25,4.575) 60(-1.75,4.575) 61(-2.25,4.575) 62(-2.75,4.575) 63(-3.25,4.575) 64(-3.75,4.575)
  rect 4.45x4.45 smd: 65(0,0)
Top Overlay:
  circle w0.25: c-5.4,3.75 r0.125
  lines w0.15: -4.66,-4.2 -4.66,-4.66 -4.16,-4.66 ; -4.66,4.16 -4.66,4.66 -4.2,4.66 ; 4.16,4.66 4.66,4.66 4.66,4.2 ; 4.2,-4.66 4.66,-4.66 4.66,-4.16
M13_Assembly_Info:
  circle w0.1: c-3.83,3.75 r0.5
  lines w0.1: -4.535,-4.535 4.535,-4.535 4.535,4.535 -4.535,4.535 -4.535,-4.535
M15_Country_Yard:
  lines w0.1: -0.5,0 0.5,0 ; 0,-0.5 0,0.5 ; -5.1,-5.1 5.1,-5.1 5.1,5.1 -5.1,5.1 -5.1,-5.1
3D body: height 1, standoff 0.05, extent -4.535,-4.535 4.535,4.535

## QFN65P400X400X100-16M [mm] "QFN, 16-Leads, Body 4.0x4.0mm (max), Pitch 0.65mm, IPC Low Density"
height 1
pads (17):
  rect 0.95x0.4 smd: 1(-1.975,0.975)
  oval 0.95x0.4 smd: 2(-1.975,0.325) 3(-1.975,-0.325) 4(-1.975,-0.975) 9(1.975,-0.975) 10(1.975,-0.325) 11(1.975,0.325) 12(1.975,0.975)
  oval 0.4x0.95 smd: 5(-0.975,-1.975) 6(-0.325,-1.975) 7(0.325,-1.975) 8(0.975,-1.975) 13(0.975,1.975) 14(0.325,1.975) 15(-0.325,1.975) 16(-0.975,1.975)
  rect 2.3x2.3 smd: 17(0,0)
Top Overlay:
  circle w0.25: c-3,0.975 r0.125
  lines w0.2: -2,-1.6 -2,-2 -1.6,-2 ; -2,1.6 -2,2 -1.6,2 ; 1.6,-2 2,-2 2,-1.6 ; 1.6,2 2,2 2,1.6
M13_Assembly_Info:
  circle w0.1: c-1.05,1.05 r0.5
  lines w0.1: -2,-2 2,-2 2,2 -2,2 -2,-2
M15_Country_Yard:
  lines w0.1: -0.5,0 0.5,0 ; 0,-0.5 0,0.5 ; -2.7,-2.7 2.7,-2.7 2.7,2.7 -2.7,2.7 -2.7,-2.7
3D body: height 1, standoff 0.05, extent -2,-2 2,2

## QFN65P700X700X100-32N [mm] "QFN, 32-Leads, Body 7.0x7.0mm (max), Pitch 0.65mm, IPC Medium Density"
height 1
pads (33):
  rect 0.8x0.35 smd: 1(-3.55,2.275)
  oval 0.8x0.35 smd: 2(-3.55,1.625) 3(-3.55,0.975) 4(-3.55,0.325) 5(-3.55,-0.325) 6(-3.55,-0.975) 7(-3.55,-1.625) 8(-3.55,-2.275) 17(3.55,-2.275) 18(3.55,-1.625) 19(3.55,-0.975) 20(3.55,-0.325) 21(3.55,0.325) 22(3.55,0.975) 23(3.55,1.625) 24(3.55,2.275)
  oval 0.35x0.8 smd: 9(-2.275,-3.55) 10(-1.625,-3.55) 11(-0.975,-3.55) 12(-0.325,-3.55) 13(0.325,-3.55) 14(0.975,-3.55) 15(1.625,-3.55) 16(2.275,-3.55) 25(2.275,3.55) 26(1.625,3.55) 27(0.975,3.55) 28(0.325,3.55) 29(-0.325,3.55) 30(-0.975,3.55) 31(-1.625,3.55) 32(-2.275,3.55)
  rect 4.9x4.9 smd: 33(0,0)
Top Overlay:
  circle w0.25: c-4.45,2.275 r0.125
  lines w0.2: -3.55,-3.075 -3.55,-3.55 -3.075,-3.55 ; -3.55,3.075 -3.55,3.55 -3.075,3.55 ; 3.075,-3.55 3.55,-3.55 3.55,-3.075 ; 3.075,3.55 3.55,3.55 3.55,3.075
M13_Assembly_Info:
  circle w0.1: c-2.585,2.585 r0.5
  lines w0.1: -3.535,-3.535 -3.535,3.535 3.535,3.535 3.535,-3.535 -3.535,-3.535
M15_Country_Yard:
  lines w0.1: -0.5,0 0.5,0 ; 0,-0.5 0,0.5 ; -4.1,-4.1 -4.1,4.1 4.1,4.1 4.1,-4.1 -4.1,-4.1
3D body: height 1, standoff 0.05, extent -3.535,-3.535 3.535,3.535

## QFN127P600-8N [mm]
height 0.9
pads (65):
  oval 0.8x0.2 smd: 1(-3.95,3) 2(-3.95,2.6) 3(-3.95,2.2) 4(-3.95,1.8) 5(-3.95,1.4) 6(-3.95,1) 7(-3.95,0.6) 8(-3.95,0.2) 9(-3.95,-0.2) 10(-3.95,-0.6) 11(-3.95,-1) 12(-3.95,-1.4) 13(-3.95,-1.8) 14(-3.95,-2.2) 15(-3.95,-2.6) 16(-3.95,-3) 33(3.95,-3) 34(3.95,-2.6) 35(3.95,-2.2) 36(3.95,-1.8) 37(3.95,-1.4) 38(3.95,-1) 39(3.95,-0.6) 40(3.95,-0.2) 41(3.95,0.2) 42(3.95,0.6) 43(3.95,1) 44(3.95,1.4) 45(3.95,1.8) 46(3.95,2.2) 47(3.95,2.6) 48(3.95,3)
  oval 0.2x0.8 smd: 17(-3,-3.95) 18(-2.6,-3.95) 19(-2.2,-3.95) 20(-1.8,-3.95) 21(-1.4,-3.95) 22(-1,-3.95) 23(-0.6,-3.95) 24(-0.2,-3.95) 25(0.2,-3.95) 26(0.6,-3.95) 27(1,-3.95) 28(1.4,-3.95) 29(1.8,-3.95) 30(2.2,-3.95) 31(2.6,-3.95) 32(3,-3.95) 49(3,3.95) 50(2.6,3.95) 51(2.2,3.95) 52(1.8,3.95) 53(1.4,3.95) 54(1,3.95) 55(0.6,3.95) 56(0.2,3.95) 57(-0.2,3.95) 58(-0.6,3.95) 59(-1,3.95) 60(-1.4,3.95) 61(-1.8,3.95) 62(-2.2,3.95) 63(-2.6,3.95) 64(-3,3.95)
  rect 6.3x6.3 smd: 65(0,0)
Top Overlay:
  circle w0.25: c-4.9,3 r0.125
  lines w0.2: -4.05,-3.5 -4.05,-4.05 -3.5,-4.05 ; -4.05,3.5 -4.05,4.05 -3.5,4.05 ; 3.5,-4.05 4.05,-4.05 4.05,-3.5 ; 3.5,4.05 4.05,4.05 4.05,3.5
M13_Assembly_Info:
  circle w0.1: c-3.085,3.085 r0.5
  lines w0.1: -4.035,-4.035 -4.035,4.035 4.035,4.035 4.035,-4.035 -4.035,-4.035
M15_Country_Yard:
  lines w0.1: -0.5,0 0.5,0 ; 0,-0.5 0,0.5 ; -4.6,-4.6 -4.6,4.6 4.6,4.6 4.6,-4.6 -4.6,-4.6
3D body: height 0.9, standoff 0.05, extent -4.035,-4.035 4.035,4.035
